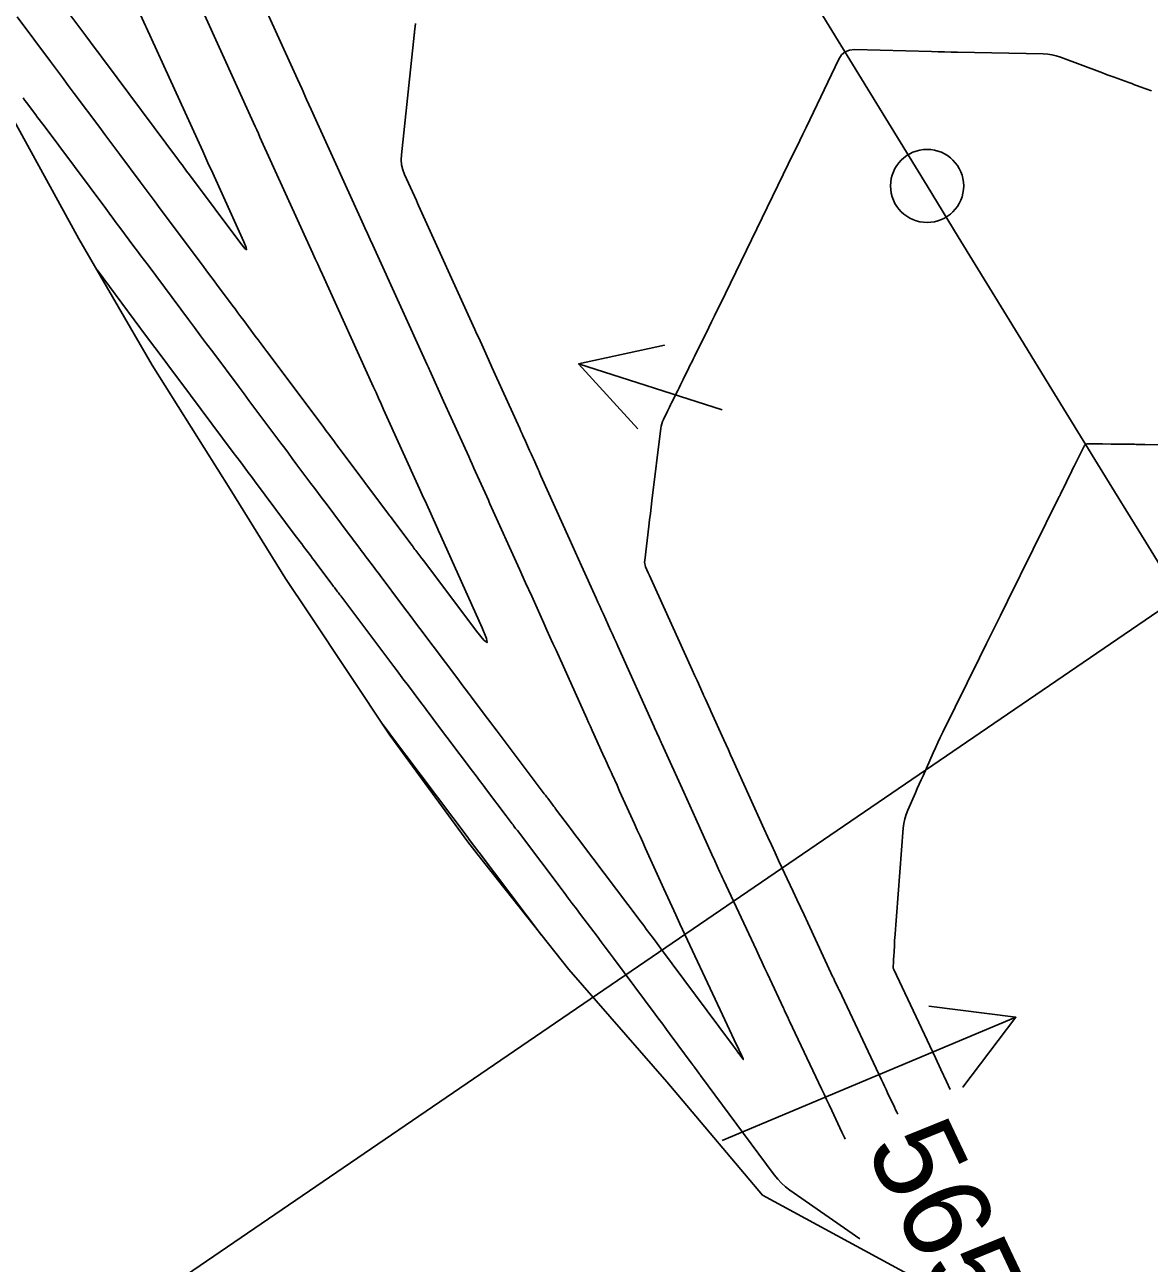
# Model space of a CAD drawing. Extents: x 954385 to 988206, y 1868364 to 1924553.
# Drawn here: x 957159.4 to 957236.3, y 1920710.5 to 1920795.3 of the extents above; entities that cross this region are included whole.
import ezdxf

# ---------------------------------------------------------------- set-up
doc = ezdxf.new("R2010")
doc.units = 0
for name, color, linetype in [('Default', 7, 'Continuous'), ('Ex_Contour Labels', 7, 'Continuous'), ('Ex_Major Contours', 7, 'Continuous'), ('Ex_Minor Contours', 7, 'Continuous'), ('Perimeter', 7, 'Continuous'), ('Prop_Horiz Alignment', 7, 'Continuous'), ('Slopes', 7, 'Continuous')]:
    doc.layers.add(name, color=color, linetype=linetype)

msp = doc.modelspace()

# ---------------------------------------------------------------- linework, layer by layer
at = {"layer": 'Default'}
msp.add_line((957221.14, 1920784.239), (956045.796, 1922705.182), dxfattribs=at)
msp.add_arc((966995.782, 1926764.927), 11459.156, 211.4606918, 214.0750737, dxfattribs=at)
at = {"layer": 'Ex_Major Contours'}
for points in [[(957219.134, 1920720.733), (957219.066, 1920720.879), (957218.987, 1920721.045), (957218.909, 1920721.211), (957218.44, 1920722.204), (957218.336, 1920722.425), (957218.232, 1920722.646), (957218.127, 1920722.867), (957218.023, 1920723.088), (957215.118, 1920729.242), (957215.103, 1920729.272), (957215.089, 1920729.303), (957215.074, 1920729.334), (957215.059, 1920729.365), (957214.808, 1920729.892), (957214.781, 1920729.949), (957214.755, 1920730.006), (957214.728, 1920730.063), (957214.701, 1920730.12), (957212.969, 1920733.835), (957212.72, 1920734.367), (957212.472, 1920734.899), (957212.224, 1920735.431), (957211.976, 1920735.963), (957210.983, 1920738.092), (957210.736, 1920738.624), (957210.49, 1920739.158), (957210.245, 1920739.691), (957210.002, 1920740.226), (957207.85, 1920744.982), (957207.697, 1920745.32), (957207.544, 1920745.659), (957207.39, 1920745.997), (957207.237, 1920746.335), (957206.342, 1920748.312), (957206.294, 1920748.418), (957205.976, 1920749.12), (957205.935, 1920749.21), (957205.895, 1920749.3), (957205.854, 1920749.391), (957205.813, 1920749.481), (957205.4, 1920750.395), (957205.236, 1920750.76), (957205.071, 1920751.125), (957202.251, 1920757.376), (957202.16, 1920757.578), (957202.068, 1920757.781), (957201.885, 1920758.187), (957201.847, 1920758.289), (957201.823, 1920758.394), (957201.815, 1920758.501), (957201.821, 1920758.611), (957202.107, 1920760.97), (957202.159, 1920761.4), (957202.212, 1920761.83), (957202.264, 1920762.26), (957202.316, 1920762.69), (957202.919, 1920767.659), (957202.945, 1920767.815), (957202.983, 1920767.967), (957203.034, 1920768.115), (957203.098, 1920768.26), (957203.379, 1920768.83), (957203.449, 1920768.972), (957203.52, 1920769.115), (957203.59, 1920769.257), (957203.661, 1920769.399), (957204.079, 1920770.246), (957204.173, 1920770.435), (957204.266, 1920770.623), (957204.359, 1920770.812), (957204.453, 1920771.001), (957204.845, 1920771.795), (957204.941, 1920771.99), (957205.038, 1920772.185), (957205.134, 1920772.38), (957205.231, 1920772.575), (957206.207, 1920774.551), (957206.401, 1920774.946), (957206.595, 1920775.341), (957206.788, 1920775.736), (957206.981, 1920776.132), (957212.011, 1920786.478), (957212.223, 1920786.915), (957212.434, 1920787.352), (957212.646, 1920787.79), (957212.856, 1920788.228), (957215.097, 1920792.9), (957215.287, 1920793.197), (957215.531, 1920793.406), (957215.828, 1920793.528), (957216.179, 1920793.562), (957221.44, 1920793.429), (957221.885, 1920793.418), (957222.33, 1920793.407), (957222.776, 1920793.397), (957223.221, 1920793.388), (957229.088, 1920793.27), (957229.386, 1920793.252), (957229.68, 1920793.208), (957229.969, 1920793.14), (957230.253, 1920793.047), (957233.133, 1920791.968), (957233.332, 1920791.894), (957233.53, 1920791.821), (957233.729, 1920791.747), (957233.927, 1920791.675), (957234.939, 1920791.306), (957235.133, 1920791.235), (957235.328, 1920791.163), (957235.523, 1920791.092), (957235.718, 1920791.021), (957236.498, 1920790.737)], [(957194.757, 1920732.993), (957190.499, 1920738.637), (957190.481, 1920738.661), (957189.893, 1920739.441), (957189.772, 1920739.602), (957189.745, 1920739.638), (957184.435, 1920746.692), (957184.391, 1920746.751), (957183.923, 1920747.374)]]:
    msp.add_lwpolyline(points, dxfattribs=at)
at = {"layer": 'Ex_Minor Contours'}
for points in [[(957159.083, 1920800.544), (957163.12, 1920795.135), (957163.596, 1920794.497), (957164.231, 1920793.647), (957164.39, 1920793.434), (957164.549, 1920793.221), (957164.707, 1920793.009), (957164.866, 1920792.796), (957169.93, 1920786.008), (957170.055, 1920785.841), (957170.179, 1920785.674), (957170.491, 1920785.256), (957170.678, 1920785.005), (957174.195, 1920780.294), (957174.459, 1920779.965), (957174.581, 1920779.876), (957174.562, 1920780.026), (957174.401, 1920780.416), (957172.158, 1920785.352), (957172.016, 1920785.666), (957171.873, 1920785.979), (957171.73, 1920786.293), (957171.588, 1920786.607), (957167.724, 1920795.101), (957167.679, 1920795.2), (957163.801, 1920803.734)], [(957159.307, 1920790.256), (957159.43, 1920790.09), (957159.554, 1920789.924), (957159.678, 1920789.758), (957160.174, 1920789.094), (957160.298, 1920788.928), (957160.421, 1920788.762), (957160.545, 1920788.596), (957160.669, 1920788.43), (957164.954, 1920782.688), (957165.195, 1920782.365), (957165.436, 1920782.042), (957165.678, 1920781.718), (957165.919, 1920781.395), (957166.883, 1920780.103), (957167.124, 1920779.78), (957167.366, 1920779.457), (957167.607, 1920779.134), (957167.848, 1920778.811), (957170.615, 1920775.101), (957171.029, 1920774.547), (957171.442, 1920773.993), (957171.856, 1920773.439), (957172.27, 1920772.885), (957174.077, 1920770.464), (957174.415, 1920770.013), (957174.752, 1920769.561), (957175.09, 1920769.109), (957175.427, 1920768.657), (957176.937, 1920766.635), (957177.195, 1920766.291), (957177.452, 1920765.947), (957177.709, 1920765.603), (957177.967, 1920765.259), (957178.996, 1920763.883), (957179.254, 1920763.539), (957179.511, 1920763.195), (957179.769, 1920762.851), (957180.026, 1920762.507), (957181.602, 1920760.403), (957181.693, 1920760.281), (957181.785, 1920760.159), (957181.876, 1920760.038), (957181.967, 1920759.916), (957182.333, 1920759.429), (957182.425, 1920759.308), (957182.516, 1920759.186), (957182.607, 1920759.064), (957182.699, 1920758.943), (957183.24, 1920758.221), (957183.361, 1920758.06), (957183.482, 1920757.899), (957183.602, 1920757.739), (957183.723, 1920757.578), (957185.256, 1920755.539), (957185.552, 1920755.146), (957185.847, 1920754.753), (957186.143, 1920754.359), (957186.439, 1920753.966), (957189.105, 1920750.419), (957189.323, 1920750.128), (957189.541, 1920749.838), (957189.76, 1920749.548), (957189.978, 1920749.257), (957190.852, 1920748.096), (957191.07, 1920747.806), (957191.289, 1920747.516), (957191.507, 1920747.226), (957191.726, 1920746.936), (957194.954, 1920742.653), (957195.031, 1920742.551), (957195.128, 1920742.423), (957195.185, 1920742.346), (957195.493, 1920741.937), (957195.551, 1920741.86), (957195.609, 1920741.783), (957195.667, 1920741.706), (957195.724, 1920741.63), (957196.74, 1920740.283), (957196.929, 1920740.034), (957197.117, 1920739.784), (957197.306, 1920739.534), (957197.495, 1920739.284), (957201.435, 1920734.064), (957201.559, 1920733.899), (957201.683, 1920733.735), (957201.806, 1920733.57), (957201.929, 1920733.405), (957202.42, 1920732.745), (957202.666, 1920732.414), (957202.911, 1920732.084), (957207.693, 1920725.655), (957207.71, 1920725.632), (957208.136, 1920725.051), (957208.165, 1920725.012), (957208.251, 1920724.895), (957208.527, 1920724.523), (957208.556, 1920724.487), (957208.569, 1920724.476), (957208.567, 1920724.493), (957208.548, 1920724.535), (957208.363, 1920724.928), (957208.308, 1920725.044), (957208.28, 1920725.102), (957208.253, 1920725.16), (957207.976, 1920725.742), (957207.949, 1920725.798), (957207.939, 1920725.819), (957206.976, 1920727.885), (957204.231, 1920733.768), (957203.954, 1920734.365), (957203.678, 1920734.963), (957203.404, 1920735.561), (957203.132, 1920736.16), (957201.883, 1920738.919), (957201.693, 1920739.338), (957201.504, 1920739.757), (957201.314, 1920740.176), (957201.125, 1920740.594), (957200.108, 1920742.841), (957199.927, 1920743.242), (957199.59, 1920743.984), (957199.547, 1920744.08), (957199.503, 1920744.177), (957199.46, 1920744.273), (957199.416, 1920744.369), (957199.164, 1920744.924), (957199.135, 1920744.987), (957199.088, 1920745.091), (957199.06, 1920745.154), (957198.351, 1920746.724), (957198.23, 1920746.992), (957198.109, 1920747.261), (957197.988, 1920747.53), (957197.866, 1920747.798), (957195.757, 1920752.472), (957195.549, 1920752.933), (957195.341, 1920753.395), (957195.132, 1920753.857), (957194.924, 1920754.318), (957194.091, 1920756.165), (957193.675, 1920757.089), (957193.258, 1920758.012), (957191.239, 1920762.49), (957191.183, 1920762.614), (957191.127, 1920762.739), (957190.902, 1920763.237), (957190.254, 1920764.676), (957190.136, 1920764.937), (957190.019, 1920765.197), (957189.901, 1920765.458), (957189.784, 1920765.718), (957188.584, 1920768.37), (957188.066, 1920769.516), (957187.12, 1920771.607), (957187.075, 1920771.707), (957187.03, 1920771.807), (957186.984, 1920771.907), (957186.939, 1920772.007), (957183.226, 1920780.187), (957183.045, 1920780.585), (957182.865, 1920780.982), (957182.685, 1920781.379), (957182.504, 1920781.777), (957179.327, 1920788.769), (957179.012, 1920789.462), (957178.697, 1920790.155), (957178.382, 1920790.848), (957178.067, 1920791.541), (957174.938, 1920798.419)], [(957171.589, 1920796.193), (957175.062, 1920788.557), (957175.174, 1920788.312), (957175.285, 1920788.067), (957175.396, 1920787.823), (957175.507, 1920787.578), (957179.124, 1920779.618), (957179.289, 1920779.256), (957179.453, 1920778.894), (957179.617, 1920778.532), (957179.782, 1920778.171), (957183.271, 1920770.482), (957183.445, 1920770.101), (957183.618, 1920769.719), (957183.791, 1920769.337), (957183.963, 1920768.955), (957186.419, 1920763.526), (957186.513, 1920763.318), (957186.607, 1920763.11), (957186.701, 1920762.902), (957186.794, 1920762.695), (957187.668, 1920760.756), (957187.72, 1920760.641), (957187.772, 1920760.526), (957187.823, 1920760.41), (957187.875, 1920760.295), (957190.71, 1920754.009), (957191.006, 1920753.285), (957191.039, 1920753.004), (957190.809, 1920753.168), (957190.316, 1920753.776), (957186.705, 1920758.581), (957186.572, 1920758.758), (957186.439, 1920758.935), (957186.173, 1920759.289), (957186.107, 1920759.377), (957186.04, 1920759.466), (957185.974, 1920759.554), (957185.907, 1920759.643), (957184.595, 1920761.391), (957184.545, 1920761.458), (957184.495, 1920761.525), (957184.394, 1920761.659), (957184.344, 1920761.725), (957184.294, 1920761.792), (957180.981, 1920766.217), (957180.884, 1920766.347), (957180.787, 1920766.476), (957180.69, 1920766.606), (957180.593, 1920766.735), (957180.205, 1920767.253), (957180.108, 1920767.383), (957180.011, 1920767.512), (957179.914, 1920767.642), (957179.817, 1920767.772), (957175.976, 1920772.914), (957175.779, 1920773.179), (957175.581, 1920773.443), (957175.384, 1920773.708), (957175.186, 1920773.972), (957174.396, 1920775.03), (957174.199, 1920775.294), (957174.002, 1920775.559), (957173.804, 1920775.823), (957173.607, 1920776.087), (957172.542, 1920777.514), (957172.299, 1920777.84), (957172.056, 1920778.166), (957171.813, 1920778.492), (957171.569, 1920778.818), (957168.684, 1920782.683), (957168.34, 1920783.145), (957167.995, 1920783.607), (957167.65, 1920784.069), (957167.306, 1920784.53), (957165.927, 1920786.378), (957165.583, 1920786.839), (957165.238, 1920787.301), (957164.893, 1920787.763), (957164.549, 1920788.225), (957162.802, 1920790.567), (957162.396, 1920791.112), (957161.99, 1920791.656), (957161.583, 1920792.2), (957161.177, 1920792.744), (957158.898, 1920795.797)], [(957186.141, 1920795.356), (957186.079, 1920794.774), (957186.074, 1920794.719), (957186.068, 1920794.665), (957186.062, 1920794.611), (957186.056, 1920794.556), (957185.176, 1920786.368), (957185.161, 1920786.018), (957185.192, 1920785.675), (957185.27, 1920785.34), (957185.394, 1920785.013), (957186.201, 1920783.237), (957186.277, 1920783.069), (957186.353, 1920782.902), (957190.209, 1920774.407), (957190.325, 1920774.151), (957190.442, 1920773.894), (957190.558, 1920773.638), (957190.674, 1920773.381), (957191.138, 1920772.355), (957191.37, 1920771.842), (957191.602, 1920771.328), (957193.27, 1920767.642), (957193.35, 1920767.464), (957193.431, 1920767.285), (957193.511, 1920767.107), (957193.592, 1920766.928), (957193.944, 1920766.145), (957194.009, 1920766.001), (957194.074, 1920765.857), (957194.139, 1920765.712), (957194.204, 1920765.568), (957194.464, 1920764.991), (957194.529, 1920764.847), (957194.594, 1920764.703), (957194.659, 1920764.558), (957194.724, 1920764.414), (957196.676, 1920760.085), (957196.884, 1920759.625), (957197.091, 1920759.165), (957197.298, 1920758.706), (957197.506, 1920758.246), (957198.504, 1920756.033), (957198.627, 1920755.76), (957198.75, 1920755.486), (957198.874, 1920755.213), (957198.997, 1920754.94), (957199.49, 1920753.847), (957199.613, 1920753.573), (957199.737, 1920753.3), (957199.86, 1920753.027), (957199.983, 1920752.754), (957202.474, 1920747.235), (957202.499, 1920747.178), (957202.817, 1920746.477), (957202.864, 1920746.374), (957202.91, 1920746.271), (957202.957, 1920746.169), (957203.003, 1920746.066), (957204.499, 1920742.762), (957204.91, 1920741.853), (957205.322, 1920740.944), (957206.424, 1920738.509), (957206.621, 1920738.074), (957206.949, 1920737.349), (957207.015, 1920737.204), (957207.081, 1920737.059), (957207.148, 1920736.915), (957207.215, 1920736.77), (957209.458, 1920731.962), (957209.647, 1920731.556), (957209.836, 1920731.151), (957210.025, 1920730.745), (957210.214, 1920730.339), (957211.312, 1920727.988), (957211.331, 1920727.946), (957211.35, 1920727.905), (957211.37, 1920727.864), (957211.389, 1920727.823), (957211.64, 1920727.297), (957211.662, 1920727.25), (957211.684, 1920727.203), (957211.707, 1920727.156), (957211.729, 1920727.11), (957213.913, 1920722.481), (957214.088, 1920722.111), (957214.263, 1920721.74), (957214.438, 1920721.37), (957214.613, 1920720.999), (957215.313, 1920719.517), (957215.488, 1920719.146), (957215.541, 1920719.033)], [(957216.532, 1920712.206), (957211.758, 1920715.545), (957211.459, 1920715.773), (957211.18, 1920716.022), (957210.923, 1920716.293), (957210.687, 1920716.587), (957209.111, 1920718.715), (957205.649, 1920723.387), (957205.626, 1920723.418), (957205.603, 1920723.45), (957205.58, 1920723.481), (957205.557, 1920723.512), (957205.466, 1920723.636), (957205.42, 1920723.699), (957205.374, 1920723.761), (957205.211, 1920723.981), (957205.177, 1920724.028), (957205.142, 1920724.075), (957205.107, 1920724.122), (957205.072, 1920724.169), (957203.574, 1920726.183), (957203.313, 1920726.535), (957203.052, 1920726.886), (957202.79, 1920727.237), (957202.529, 1920727.588), (957199.687, 1920731.41), (957199.407, 1920731.786), (957199.126, 1920732.161), (957198.845, 1920732.535), (957198.564, 1920732.909), (957197.435, 1920734.403), (957197.153, 1920734.777), (957196.871, 1920735.151), (957196.589, 1920735.524), (957196.307, 1920735.898), (957193.112, 1920740.133), (957193.052, 1920740.212), (957192.993, 1920740.291), (957192.875, 1920740.448), (957192.815, 1920740.527), (957192.756, 1920740.606), (957192.483, 1920740.968), (957192.341, 1920741.156), (957191.007, 1920742.927), (957190.768, 1920743.243), (957190.53, 1920743.559), (957190.292, 1920743.875), (957190.054, 1920744.192), (957187.45, 1920747.651), (957187.217, 1920747.961), (957186.985, 1920748.27), (957186.752, 1920748.58), (957186.519, 1920748.889), (957185.588, 1920750.128), (957185.356, 1920750.437), (957185.123, 1920750.747), (957184.89, 1920751.056), (957184.658, 1920751.366), (957181.032, 1920756.188), (957180.978, 1920756.26), (957180.923, 1920756.333), (957180.869, 1920756.405), (957180.814, 1920756.478), (957180.596, 1920756.769), (957180.541, 1920756.841), (957180.487, 1920756.914), (957180.432, 1920756.987), (957180.378, 1920757.059), (957179.473, 1920758.263), (957179.349, 1920758.428), (957179.225, 1920758.593), (957179.101, 1920758.758), (957178.978, 1920758.923), (957178.483, 1920759.583), (957178.36, 1920759.749), (957178.236, 1920759.914), (957178.112, 1920760.079), (957177.989, 1920760.244), (957175.135, 1920764.057), (957175.014, 1920764.219), (957174.892, 1920764.381), (957174.771, 1920764.543), (957174.65, 1920764.705), (957174.165, 1920765.354), (957173.923, 1920765.678), (957173.681, 1920766.003), (957170.015, 1920770.912), (957169.449, 1920771.669), (957168.883, 1920772.427), (957168.318, 1920773.185), (957167.752, 1920773.943), (957164.36, 1920778.49)], [(957222.727, 1920722.434), (957222.468, 1920722.982), (957222.087, 1920723.788), (957221.707, 1920724.594), (957218.86, 1920730.628), (957218.84, 1920730.678), (957218.826, 1920730.729), (957218.82, 1920730.782), (957218.82, 1920730.835), (957218.836, 1920731.108), (957218.846, 1920731.271), (957218.867, 1920731.613), (957218.869, 1920731.636), (957218.87, 1920731.658), (957218.874, 1920731.748), (957218.9, 1920732.358), (957218.905, 1920732.464), (957218.911, 1920732.569), (957218.918, 1920732.675), (957218.926, 1920732.78), (957219.507, 1920740.312), (957219.545, 1920740.629), (957219.609, 1920740.939), (957219.7, 1920741.243), (957219.817, 1920741.541), (957220.337, 1920742.717), (957220.467, 1920743.011), (957220.598, 1920743.305), (957220.728, 1920743.599), (957220.858, 1920743.893), (957221.549, 1920745.449), (957221.709, 1920745.805), (957221.873, 1920746.16), (957222.041, 1920746.513), (957222.212, 1920746.864), (957224.727, 1920751.961), (957225.204, 1920752.927), (957225.681, 1920753.893), (957226.159, 1920754.859), (957226.636, 1920755.825), (957230.154, 1920762.942), (957230.18, 1920762.994), (957230.206, 1920763.047), (957230.231, 1920763.099), (957230.257, 1920763.152), (957230.385, 1920763.414), (957230.436, 1920763.519), (957230.462, 1920763.572), (957230.88, 1920764.429), (957230.959, 1920764.589), (957231.038, 1920764.75), (957231.116, 1920764.91), (957231.196, 1920765.07), (957231.85, 1920766.389), (957231.911, 1920766.481), (957231.987, 1920766.547), (957232.08, 1920766.585), (957232.19, 1920766.598), (957232.66, 1920766.593), (957232.778, 1920766.592), (957232.895, 1920766.591), (957233.013, 1920766.59), (957233.13, 1920766.589), (957233.738, 1920766.584), (957233.879, 1920766.583), (957234.019, 1920766.582), (957234.159, 1920766.58), (957234.3, 1920766.578), (957235.331, 1920766.563), (957235.447, 1920766.561), (957235.564, 1920766.56), (957235.797, 1920766.557), (957235.856, 1920766.556), (957235.914, 1920766.555), (957235.972, 1920766.555), (957236.031, 1920766.554), (957240.646, 1920766.513)]]:
    msp.add_lwpolyline(points, dxfattribs=at)
at = {"layer": 'Perimeter'}
msp.add_lwpolyline([(957220.044, 1920709.686), (957209.88, 1920715.201), (957203.844, 1920722.364), (957203.326, 1920722.955), (957196.631, 1920730.624), (957190.358, 1920738.556), (957189.726, 1920739.365), (957184.387, 1920746.677), (957178.815, 1920755.042), (957177.254, 1920757.387), (957173.459, 1920763.504), (957168.141, 1920771.973), (957163.121, 1920780.625), (957158.307, 1920789.403)], dxfattribs=at)
at = {"layer": 'Prop_Horiz Alignment'}
msp.add_circle((957221.14, 1920784.239), 2.5, dxfattribs=at)
at = {"layer": 'Slopes'}
for points in [[(957207.131, 1920768.928), (957197.304, 1920772.068), (957203.167, 1920773.344), (957197.304, 1920772.068), (957201.341, 1920767.629)], [(957257.131, 1920768.928), (957121.717, 1920676.45), (957124.316, 1920681.858), (957121.717, 1920676.45), (957127.7, 1920676.903)], [(957207.131, 1920718.928), (957227.216, 1920727.371), (957223.589, 1920722.592), (957227.216, 1920727.371), (957221.264, 1920728.123)]]:
    msp.add_lwpolyline(points, dxfattribs=at)

# ---------------------------------------------------------------- texts
at = {"layer": 'Ex_Contour Labels'}
msp.add_text('565', height=6, rotation=295.32794, dxfattribs=at).set_placement((957216.881, 1920718.482))

doc.saveas('drawing.dxf')
